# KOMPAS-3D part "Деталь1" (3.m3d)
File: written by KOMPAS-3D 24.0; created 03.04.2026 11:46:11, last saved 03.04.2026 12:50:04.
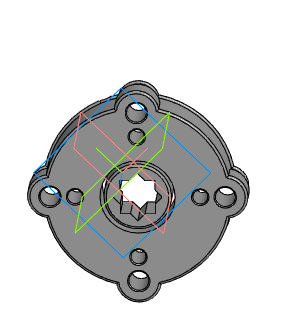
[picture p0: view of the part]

Document properties: Автор: R2D2; Полное имя файла: E:\Работа\Зайцев\Аксессуары для пневмоприводов\Ручной дублер DN.ru\MON1-250-T26-ISO Ручной дублер DN.ru\исходные материалы\3.m3d

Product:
- Body: Тело 2  | qty 1
    Масса: 0.512719
- Part/product: Деталь1
    Масса: 5.630796
    additional columns: Типовые

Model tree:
1. Операция без истории:1
2. Элемент выдавливания:1  (with: Грань.Операция без истории:1)
     Расстояние 1 = 0.5
3. Эскиз:1  (with: Ребро.Операция без истории:1)
4. Элемент выдавливания:2
     Расстояние 1 = 105; Расстояние 2 = 45
5. Эскиз:2  (with: Грань.Операция без истории:1)
6. Элемент выдавливания:3  (with: Грань.Операция без истории:1)
     Расстояние 2 = 19
7. Эскиз:3  (with: Ребро.Операция без истории:1)
8. Элемент выдавливания:4
     Расстояние 1 = 500
9. Эскиз:4  (with: Грань.Операция без истории:1, Ребро.Операция без истории:1)
10. Элемент выдавливания:5
     Расстояние 2 = 10
11. Массив по концентрической сетке:1  (with: Элемент выдавливания:5, Грань.Операция без истории:1)  (4 pattern instances)
     Шаг 2 = 360
12. Скругление:1  (with: Ребро.Элемент выдавливания:5)  (labels: Ребро.Элемент выдавливания:5.Экземпляр ( 1, 2 ); Ребро.Элемент выдавливания:5.Экземпляр ( 1, 3 ); Ребро.Элемент выдавливания:5.Экземпляр ( 1, 4 ))
     Радиус = 1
